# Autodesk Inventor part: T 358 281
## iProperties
Created: 2005-12
Part Number: T 358 281
Material: 1.0308/NBK
Description: Hülse
Document SubType Name: Modeling
Designer: I.Baliuc
Manufacturer: Standard
Standards Organization: Custom
Density: 7.84 g/cm^3
Title: Hülse
Company: Mayer & Müller AG Schaltgeräte
HalbzeugNorm: DIN 2391
Zweck: Abstandshalter Blendengrundplatte
Abmessung: Rohr 14x2-22
Author: T.Messerschmitt
Revision Number: 358281
Keywords: 381014
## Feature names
1. Extrusion2
